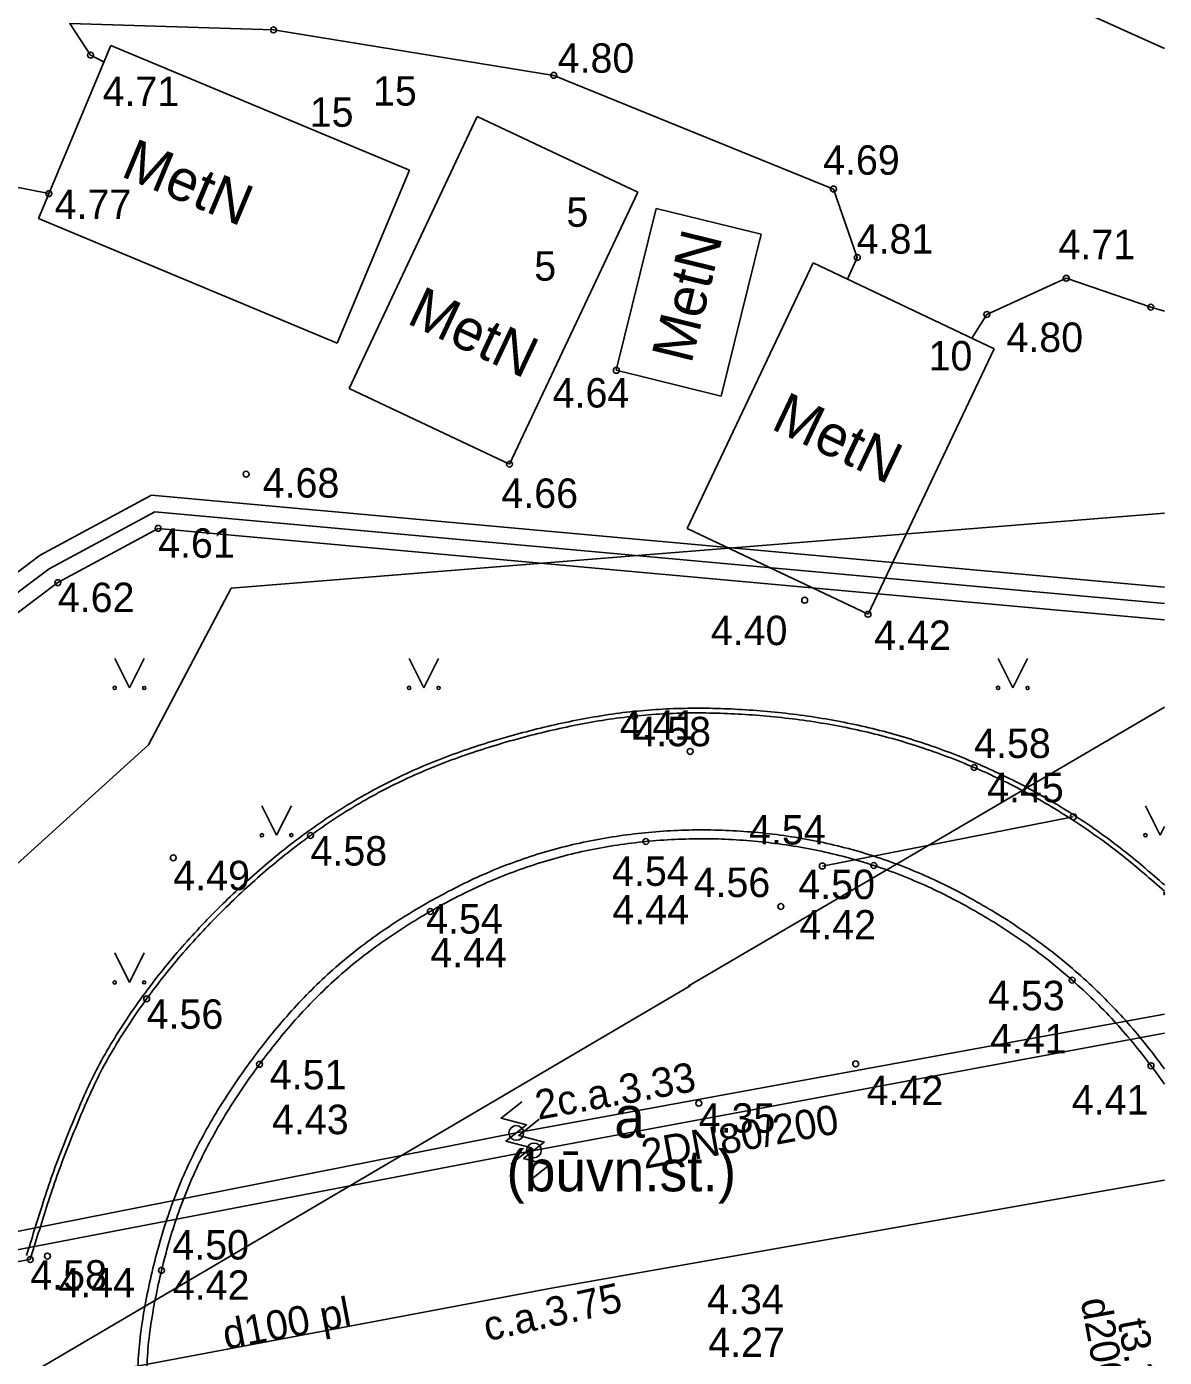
# Model space of a CAD drawing. Extents: x 484635 to 484808, y 278866 to 278977.
# Drawn here: x 484788.25 to 484807.57, y 278898.63 to 278921.23 of the extents above; entities that cross this region are included whole.
import ezdxf

# ---------------------------------------------------------------- set-up
doc = ezdxf.new("R2010")
doc.units = 0
for name, color, linetype in [('BUVE_EKAS_BPAL_####_#', 7, 'Continuous'), ('BUVE_EKAS_RAKS_TKST_#', 7, 'Continuous'), ('CELI_CAPM_####_####_#', 7, 'Continuous'), ('CELI_CMAL_####_####_#', 7, 'Continuous'), ('CELI_CSEG_####_TKST_#', 7, 'Continuous'), ('CKOM_ELEM_####_####_#', 7, 'Continuous'), ('ELEK_VADP_NEDR_####_#', 7, 'Continuous'), ('NORB_ZOGS_KONT_####_#', 7, 'Continuous'), ('NORB_ZOGS_ZSTP_####_#', 7, 'Continuous'), ('RELJ_AATZ_####_TKST_#', 7, 'Continuous'), ('RELJ_ELEM_####_####_#', 7, 'Continuous'), ('SAKK_KKAN_####_####_I', 7, 'Continuous'), ('SAKK_KKAN_####_TKST_I', 7, 'Continuous'), ('SILT_VADP_UDEN_####_I', 7, 'Continuous'), ('SILT_VADP_UDEN_TKST_I', 7, 'Continuous'), ('SKAN_VADP_PAST_TKST_I', 7, 'Continuous'), ('TERT_DIAM_####_TKST_#', 7, 'Continuous'), ('TERT_ELEM_####_####_#', 7, 'Continuous'), ('TERT_KRND_####_####_#', 7, 'Continuous'), ('UDTK_VADP_NEDR_####_#', 7, 'Continuous')]:
    doc.layers.add(name, color=color, linetype=linetype)

msp = doc.modelspace()

# ---------------------------------------------------------------- linework, layer by layer
at = {"layer": 'BUVE_EKAS_BPAL_####_#'}
for p, q in [((484789.686, 278920.907), (484788.458, 278917.971)), ((484789.686, 278920.907), (484794.753, 278918.787)), ((484793.729, 278915.082), (484795.906, 278919.7)), ((484798.63, 278918.416), (484795.906, 278919.7)), ((484793.525, 278915.851), (484794.753, 278918.787)), ((484796.453, 278913.798), (484798.63, 278918.416)), ((484798.944, 278918.14), (484798.267, 278915.392)), ((484798.944, 278918.14), (484800.724, 278917.701)), ((484788.458, 278917.971), (484793.525, 278915.851)), ((484800.724, 278917.701), (484800.046, 278914.953)), ((484799.47, 278912.707), (484801.61, 278917.215)), ((484801.61, 278917.215), (484804.681, 278915.758)), ((484802.541, 278911.25), (484804.681, 278915.758)), ((484798.267, 278915.392), (484800.046, 278914.953)), ((484793.729, 278915.082), (484796.453, 278913.798)), ((484799.47, 278912.707), (484802.541, 278911.25))]:
    msp.add_line(p, q, dxfattribs=at)
at = {"layer": 'CELI_CAPM_####_####_#'}
msp.add_line((484786.747, 278900.033), (484788.317, 278900.296), dxfattribs=at)
for points in [[(484788.255, 278900.367), (484788.517, 278901.21), (484788.673, 278901.681), (484788.846, 278902.147), (484789.032, 278902.609), (484789.228, 278903.068), (484789.44, 278903.514), (484789.681, 278903.945), (484789.944, 278904.362), (484790.228, 278904.77), (484790.854, 278905.557), (484791.543, 278906.291), (484792.26, 278906.954), (484793.028, 278907.56), (484793.866, 278908.109), (484794.755, 278908.57), (484795.675, 278908.936), (484796.62, 278909.225), (484797.586, 278909.451), (484798.565, 278909.601), (484799.544, 278909.655), (484800.523, 278909.625), (484801.513, 278909.521), (484802.498, 278909.338), (484803.45, 278909.072), (484804.375, 278908.722), (484805.267, 278908.295), (484806.117, 278907.788), (484806.918, 278907.21), (484807.573, 278906.658)], [(484788.317, 278900.296), (484788.593, 278901.185), (484788.749, 278901.655), (484788.921, 278902.118), (484789.106, 278902.578), (484789.301, 278903.035), (484789.511, 278903.477), (484789.75, 278903.904), (484790.011, 278904.317), (484790.293, 278904.722), (484790.915, 278905.505), (484791.599, 278906.234), (484792.312, 278906.893), (484793.075, 278907.495), (484793.906, 278908.04), (484794.789, 278908.497), (484795.702, 278908.86), (484796.641, 278909.148), (484797.602, 278909.373), (484798.573, 278909.521), (484799.545, 278909.575), (484800.517, 278909.545), (484801.502, 278909.442), (484802.48, 278909.26), (484803.425, 278908.996), (484804.343, 278908.649), (484805.229, 278908.224), (484806.073, 278907.721), (484806.868, 278907.147), (484807.573, 278906.55)], [(484791.093, 278891.915), (484790.321, 278896.182), (484790.246, 278896.676), (484790.194, 278897.173), (484790.161, 278897.672), (484790.143, 278898.169), (484790.155, 278898.665), (484790.207, 278899.159), (484790.291, 278899.653), (484790.4, 278900.147), (484790.526, 278900.628), (484790.676, 278901.097), (484790.85, 278901.557), (484791.053, 278902.011), (484791.531, 278902.881), (484792.088, 278903.7), (484792.712, 278904.47), (484793.41, 278905.175), (484794.191, 278905.799), (484795.034, 278906.336), (484795.899, 278906.782), (484796.807, 278907.137), (484797.774, 278907.393), (484798.754, 278907.542), (484799.749, 278907.59), (484800.745, 278907.537), (484801.722, 278907.387), (484802.686, 278907.129), (484803.612, 278906.767), (484804.493, 278906.309), (484805.33, 278905.77), (484805.725, 278905.473), (484806.108, 278905.152), (484806.826, 278904.45), (484807.467, 278903.676), (484807.573, 278903.533)], [(484791.241, 278891.942), (484790.47, 278896.202), (484790.395, 278896.69), (484790.344, 278897.182), (484790.312, 278897.674), (484790.294, 278898.166), (484790.306, 278898.654), (484790.357, 278899.141), (484790.44, 278899.626), (484790.546, 278900.112), (484790.671, 278900.586), (484790.818, 278901.047), (484790.99, 278901.5), (484791.19, 278901.947), (484791.66, 278902.803), (484792.209, 278903.61), (484792.823, 278904.369), (484793.511, 278905.062), (484794.279, 278905.676), (484795.109, 278906.205), (484795.961, 278906.645), (484796.854, 278906.993), (484797.805, 278907.246), (484798.769, 278907.392), (484799.749, 278907.439), (484800.729, 278907.387), (484801.691, 278907.239), (484802.639, 278906.986), (484803.55, 278906.629), (484804.418, 278906.178), (484805.242, 278905.648), (484805.631, 278905.355), (484806.008, 278905.039), (484806.715, 278904.347), (484807.346, 278903.586), (484807.573, 278903.274)]]:
    msp.add_spline(points, degree=3, dxfattribs=at)
at = {"layer": 'CELI_CMAL_####_####_#'}
for points in [[(484807.573, 278920.857), (484799.507, 278924.494)], [(484789.341, 278920.743), (484788.986, 278921.278), (484792.446, 278921.17), (484797.207, 278920.399), (484801.954, 278918.469), (484802.359, 278917.308), (484802.195, 278916.938)], [(484789.341, 278920.743), (484789.568, 278920.626)], [(484786.236, 278913.375), (484787.997, 278918.515), (484788.633, 278918.391)], [(484804.302, 278915.938), (484804.559, 278916.341), (484805.907, 278916.954), (484807.344, 278916.464), (484807.573, 278916.398)]]:
    msp.add_lwpolyline(points, dxfattribs=at)
at = {"layer": 'CKOM_ELEM_####_####_#'}
for points in [[(484796.662, 278902.976), (484796.312, 278902.698), (484796.745, 278902.585), (484796.394, 278902.307), (484796.827, 278902.193), (484796.476, 278901.915)], [(484796.96, 278902.68), (484796.61, 278902.401), (484797.043, 278902.289), (484796.694, 278902.01), (484797.127, 278901.898), (484796.777, 278901.619)]]:
    msp.add_lwpolyline(points, dxfattribs=at)
for centre in [(484796.569, 278902.446), (484796.869, 278902.149)]:
    msp.add_circle(centre, 0.125, dxfattribs=at)
at = {"layer": 'ELEK_VADP_NEDR_####_#'}
for points in [[(484790.322, 278909.033), (484791.728, 278911.692), (484807.573, 278912.964)], [(484780.522, 278900.153), (484790.322, 278909.033)]]:
    msp.add_lwpolyline(points, dxfattribs=at)
at = {"layer": 'NORB_ZOGS_KONT_####_#'}
for p, q in [((484788.487, 278912.252), (484790.373, 278913.272)), ((484790.373, 278913.272), (484807.573, 278911.708)), ((484788.785, 278911.787), (484790.488, 278912.709)), ((484790.488, 278912.709), (484807.573, 278911.156)), ((484770.732, 278898.963), (484788.487, 278912.252)), ((484771.089, 278898.537), (484788.785, 278911.787))]:
    msp.add_line(p, q, dxfattribs=at)
at = {"layer": 'NORB_ZOGS_ZSTP_####_#'}
for p, q in [((484788.636, 278912.019), (484790.431, 278912.99)), ((484790.431, 278912.99), (484807.573, 278911.432)), ((484770.897, 278898.742), (484788.636, 278912.019))]:
    msp.add_line(p, q, dxfattribs=at)
at = {"layer": 'RELJ_ELEM_####_####_#'}
for centre in [(484792.446, 278921.17), (484789.341, 278920.743), (484797.207, 278920.399), (484788.633, 278918.391), (484801.954, 278918.469), (484802.359, 278917.308), (484805.907, 278916.954), (484804.559, 278916.341), (484807.344, 278916.464), (484798.267, 278915.392), (484796.453, 278913.798), (484791.981, 278913.629), (484790.488, 278912.709), (484788.785, 278911.787), (484801.465, 278911.488), (484802.541, 278911.25), (484798.573, 278909.521), (484799.521, 278908.922), (484804.343, 278908.649), (484806.027, 278907.813), (484793.075, 278907.495), (484798.769, 278907.392), (484790.745, 278907.116), (484802.639, 278906.986), (484801.766, 278906.976), (484795.109, 278906.205), (484801.062, 278906.289), (484806.008, 278905.039), (484790.293, 278904.722), (484792.209, 278903.61), (484802.332, 278903.617), (484807.346, 278903.586), (484799.667, 278902.949), (484788.317, 278900.296), (484788.608, 278900.355), (484790.546, 278900.112)]:
    msp.add_circle(centre, 0.05, dxfattribs=at)
msp.add_arc((484807.615, 278906.512), 0.05, 146.0639, 213.9361, dxfattribs=at)
at = {"layer": 'SAKK_KKAN_####_####_I'}
msp.add_lwpolyline([(484761.895, 278888.193), (484770.872, 278894.886), (484788.535, 278898.187), (484797.166, 278899.809), (484807.573, 278901.643)], dxfattribs=at)
at = {"layer": 'SILT_VADP_UDEN_####_I'}
for points in [[(484807.573, 278904.462), (484796.569, 278902.446)], [(484807.573, 278904.14), (484796.869, 278902.149)], [(484796.569, 278902.446), (484784.797, 278900.122)], [(484796.869, 278902.149), (484785.084, 278899.884)]]:
    msp.add_lwpolyline(points, dxfattribs=at)
at = {"layer": 'TERT_ELEM_####_####_#'}
for p, q in [((484789.75, 278910.5), (484790, 278910)), ((484790, 278910), (484790.25, 278910.5)), ((484794.75, 278910.5), (484795, 278910)), ((484795, 278910), (484795.25, 278910.5)), ((484804.75, 278910.5), (484805, 278910)), ((484805, 278910), (484805.25, 278910.5)), ((484792.25, 278908), (484792.5, 278907.5)), ((484792.5, 278907.5), (484792.75, 278908)), ((484807.25, 278908), (484807.5, 278907.5)), ((484807.5, 278907.5), (484807.573, 278907.646)), ((484789.75, 278905.5), (484790, 278905)), ((484790, 278905), (484790.25, 278905.5))]:
    msp.add_line(p, q, dxfattribs=at)
for centre, radius in [((484789.75, 278910), 0.028), ((484790.25, 278910), 0.0263), ((484794.75, 278910), 0.028), ((484795.25, 278910), 0.0263), ((484804.75, 278910), 0.028), ((484805.25, 278910), 0.0263), ((484792.25, 278907.5), 0.028), ((484792.75, 278907.5), 0.0263), ((484807.25, 278907.5), 0.028), ((484789.75, 278905), 0.028), ((484790.25, 278905), 0.0263)]:
    msp.add_circle(centre, radius, dxfattribs=at)
at = {"layer": 'TERT_KRND_####_####_#'}
msp.add_lwpolyline([(484801.766, 278906.976), (484806.027, 278907.813)], dxfattribs=at)
at = {"layer": 'UDTK_VADP_NEDR_####_#'}
for points in [[(484799.489, 278904.934), (484807.573, 278909.671)], [(484753.238, 278876.403), (484757.275, 278880.118), (484799.521, 278904.942)]]:
    msp.add_lwpolyline(points, dxfattribs=at)

# ---------------------------------------------------------------- texts
at = {"layer": 'BUVE_EKAS_RAKS_TKST_#'}
for rotation, p in [(337.2954, (484789.833, 278918.694)), (76.1583, (484799.54, 278915.486)), (334.7606, (484794.688, 278916.2)), (334.6137, (484800.871, 278914.408))]:
    msp.add_text('MetN', height=0.7, rotation=rotation, dxfattribs=at).set_placement(p)
at = {"layer": 'CELI_CSEG_####_TKST_#'}
for s, p in [('a', (484798.232, 278902.364)), ('(būvn.st.)', (484796.401, 278901.454))]:
    msp.add_text(s, height=0.7, dxfattribs=at).set_placement(p)
at = {"layer": 'RELJ_AATZ_####_TKST_#'}
for s, p in [('4.80', (484797.272, 278920.443)), ('4.71', (484789.545, 278919.878)), ('4.69', (484801.779, 278918.712)), ('4.77', (484788.731, 278917.96)), ('4.81', (484802.349, 278917.372)), ('4.71', (484805.776, 278917.277)), ('4.80', (484804.892, 278915.703)), ('4.64', (484797.186, 278914.76)), ('4.68', (484792.263, 278913.231)), ('4.66', (484796.316, 278913.056)), ('4.61', (484790.488, 278912.209)), ('4.62', (484788.785, 278911.287)), ('4.40', (484799.872, 278910.726)), ('4.42', (484802.647, 278910.644)), ('4.41', (484798.324, 278909.122)), ('4.58', (484798.573, 278909.01)), ('4.58', (484804.343, 278908.81)), ('4.45', (484804.563, 278908.059)), ('4.54', (484800.521, 278907.342)), ('4.58', (484793.075, 278906.984)), ('4.49', (484790.745, 278906.566)), ('4.54', (484798.195, 278906.64)), ('4.56', (484799.58, 278906.449)), ('4.50', (484801.357, 278906.415)), ('4.44', (484798.201, 278905.986)), ('4.54', (484795.038, 278905.829)), ('4.42', (484801.376, 278905.729)), ('4.44', (484795.109, 278905.256)), ('4.53', (484804.578, 278904.528)), ('4.56', (484790.293, 278904.213)), ('4.41', (484804.611, 278903.795)), ('4.51', (484792.384, 278903.186)), (' 4.42', (484802.332, 278902.917)), ('4.41', (484806.002, 278902.758)), ('4.43', (484792.422, 278902.424)), ('4.35', (484799.667, 278902.449)), ('4.50', (484790.73, 278900.296)), ('4.58', (484788.317, 278899.785)), (' 4.44', (484788.608, 278899.655)), ('4.42', (484790.738, 278899.612)), ('4.34', (484799.809, 278899.371)), ('4.27', (484799.829, 278898.641))]:
    msp.add_text(s, height=0.5, dxfattribs=at).set_placement(p)
at = {"layer": 'SAKK_KKAN_####_TKST_I'}
for s, rotation, p in [('c.a.3.75', 12.49, (484796.074, 278898.907)), ('d100 pl', 10.6433, (484791.637, 278898.77))]:
    msp.add_text(s, height=0.5, rotation=rotation, dxfattribs=at).set_placement(p)
at = {"layer": 'SILT_VADP_UDEN_TKST_I'}
for s, p in [('2c.a.3.33', (484796.94, 278902.666)), ('2DN80/200', (484798.745, 278901.834))]:
    msp.add_text(s, height=0.5, rotation=10.3853, dxfattribs=at).set_placement(p)
at = {"layer": 'SKAN_VADP_PAST_TKST_I'}
for s, p in [('d200pl', (484806.151, 278899.605)), ('t3.17', (484806.779, 278899.243))]:
    msp.add_text(s, height=0.5, rotation=280.2797, dxfattribs=at).set_placement(p)
at = {"layer": 'TERT_DIAM_####_TKST_#'}
for s, p in [('15', (484794.136, 278919.885)), ('15', (484793.062, 278919.526)), ('5', (484797.42, 278917.828)), ('5', (484796.874, 278916.913)), ('10', (484803.569, 278915.389))]:
    msp.add_text(s, height=0.5, dxfattribs=at).set_placement(p)

doc.saveas('drawing.dxf')
